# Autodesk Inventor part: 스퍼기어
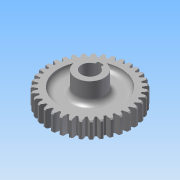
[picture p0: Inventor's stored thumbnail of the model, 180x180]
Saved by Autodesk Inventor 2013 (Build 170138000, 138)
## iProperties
Created: 2013-08
Part Number: 스퍼기어
Material: 강
Document SubType Name: Modeling
Designer: 한국산업디자인학원
Categories: <?xml version="1.0" encoding="UTF-16"?> <MemberInstance><Categories><FamilyTemplate><FamilyTemplateParameter ValueType="xs:double" Id="1" ObjectReferenceKey="da
Density: 1 g/cm^3
CustomPartVersion: 1
Author: 한국산업디자인학원
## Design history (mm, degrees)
sketch "Sketch1"
  geometry: C1 r 37 at (0, 0)
  constraints: 1 centre point
  dimensions: "d0" = 74 diameter of C1 (= da_da)
extrude "Extrusion1" new body sketch "Sketch1" distance "d1" = 15 (= da_b); taper "d2" = 0 deg
chamfer "모따기1" distance "d49" = 1; stored, may be unused: second distance "d50" = 2, angle "d51" = 45 deg
workplane "Work Plane2"
feature "피치 지름" dims "d4" = 10, "d5" = 0
workplane "Work Plane8"
workplane "Work Plane9"
feature "스퍼 기어" dims "da_b" = 15, "da_d" = 70, "da_aw" = 70, "da_da" = 74, "da_df" = 65, "da_dw" = 70, angle "da_beta" = 0 deg, "da_lefttooth" = 0, "da_righttooth" = 0
node "작업 평면11"
sketch "스케치6"
  geometry: C1 r 27.5 at (0, 0); A1 r 32.5 centre (0, 0) between (9.347, 31.127) and (7.941, 31.515) reference
  constraints: 1 centre point, 1 coincident
  dimensions: "d63" = 55 diameter of C1
extrude "돌출3" cut sketch "스케치6" distance "d65" = 5; taper "d66" = 0 deg
node "작업 평면12"
sketch "스케치3"
  geometry: C1 r 12.5 at (0, 0); 1 further point
  constraints: 1 centre point, 1 coincident
  dimensions: "d57" = 25 diameter of C1
extrude "돌출2" join sketch "스케치3" distance "d59" = 31; taper "d60" = 0 deg
sketch "스케치7"
  geometry: L1 (2.5, 7.071)-(2.5, 9.8); L2 (2.5, 9.8)-(-2.5, 9.8); L3 (-2.5, 9.8)-(-2.5, 7.071); C1 r 12.5 at (0, 0) reference; A1 r 7.5 centre (0, 0) between (2.5, 7.071) and (-2.5, 7.071)
  constraints: 6 end point, 2 parallel, 2 point on circle, 1 centre point, 1 coincident, 1 perpendicular, 1 vertical
  dimensions: "d68" = 15 diameter of A1; "d70" = 5 distance of L1.end L2.end; "d71" = 17.3 dimension on A1 L2
extrude "돌출4" cut sketch "스케치7" stored distance "d72" = 5; taper "d73" = 0 deg
fillet "모깎기1" dims "d74" = 5
body "Solid1"
mirror "대칭1"
sketch "Sketch2"
  geometry: C1 r 37 at (0, 0) reference; C2 r 35 at (0, 0)
  constraints: 1 centre point, 1 coincident
  dimensions: "d3" = 70 diameter of C2 (= da_dw)
body "Srf1"
other parameters: "d17" = 0, "d34" = 0.8976 (computed from da_z), "d39" = 0, "d41" = 0, "d47" = 0, "d48" = 0, "d52" = 3, "d67" = -7.5
